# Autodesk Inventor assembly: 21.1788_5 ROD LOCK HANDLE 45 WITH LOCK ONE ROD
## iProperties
Created: 2007-03
Part Number: 21.1788_5 ROD LOCK HANDLE 45 WITH LOCK ONE ROD
Document SubType Name: Assembly
Designer: Andy Moles
Author: Andy Moles
